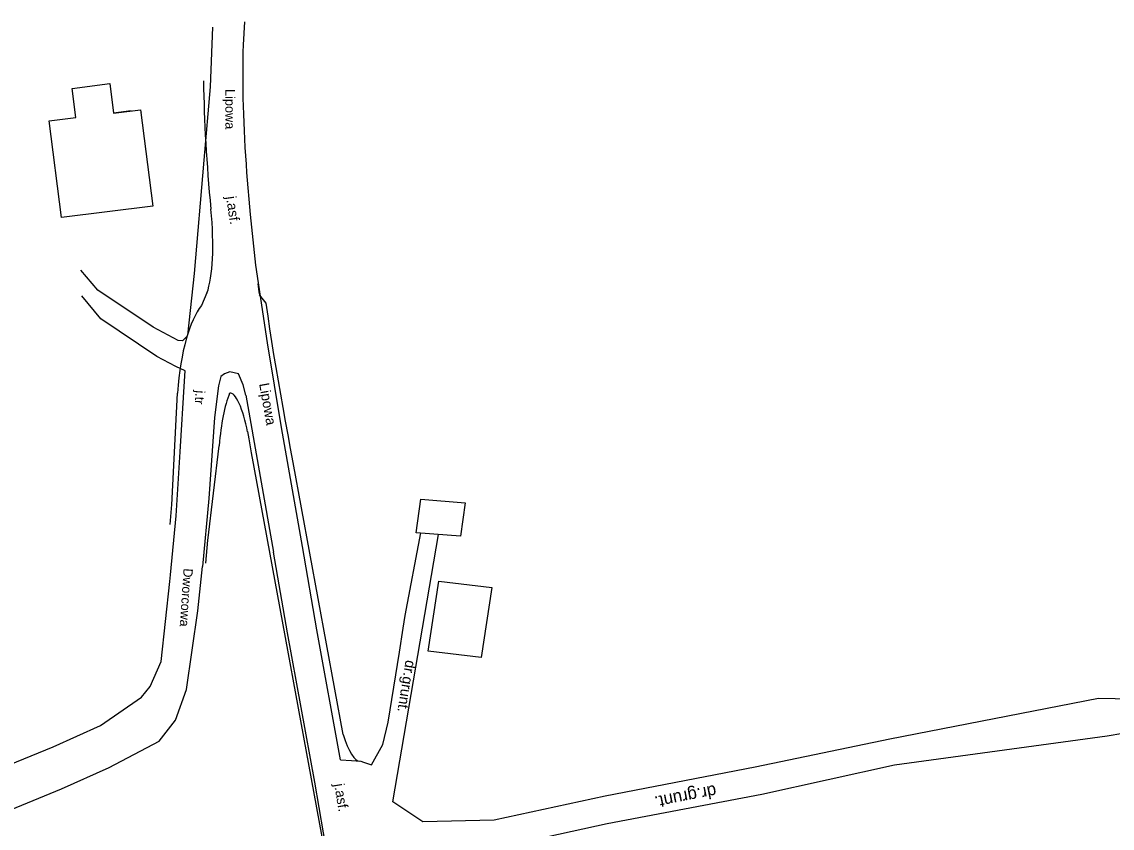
# Model space of a CAD drawing. Extents: x 6541740 to 6556805, y 5525233 to 5530361.
# Drawn here: x 6555210.5 to 6555318.7, y 5525816.1 to 5525896.2 of the extents above; entities that cross this region are included whole.
import ezdxf

# ---------------------------------------------------------------- set-up
doc = ezdxf.new("R2010")
doc.units = 0
for name, color, linetype in [('Default', 7, 'Continuous'), ('TOR_SCH-budynki', 7, 'Continuous'), ('TOR_SCH-przejazdy+drogi istniejace', 7, 'Continuous'), ('TOR_SCH-przejazdy+drogi projektowane', 7, 'Continuous')]:
    doc.layers.add(name, color=color, linetype=linetype)

# ---------------------------------------------------------------- blocks, each defined once
blk = doc.blocks.new('POINT_DISPLAY')
at = {"layer": 'Default'}
blk.add_line((0, 0), (0, 0), dxfattribs=at)

msp = doc.modelspace()

# ---------------------------------------------------------------- linework, layer by layer
at = {"layer": 'TOR_SCH-budynki'}
for p, q in [((6555215.47, 5525889.61), (6555219.19, 5525890.1)), ((6555215.84, 5525886.73), (6555215.47, 5525889.61)), ((6555219.19, 5525890.1), (6555219.58, 5525887.16)), ((6555219.58, 5525887.16), (6555222.23, 5525887.47)), ((6555221.31, 5525887.37), (6555219.58, 5525887.16)), ((6555222.23, 5525887.47), (6555223.46, 5525877.9)), ((6555213.19, 5525886.39), (6555215.84, 5525886.73)), ((6555214.4, 5525876.79), (6555213.19, 5525886.39)), ((6555223.46, 5525877.9), (6555214.4, 5525876.79))]:
    msp.add_line(p, q, dxfattribs=at)
at = {"layer": 'TOR_SCH-przejazdy+drogi istniejace'}
for p, q in [((6555232.56, 5525896.22), (6555232.43, 5525893.93)), ((6555229.21, 5525889.76), (6555229.43, 5525895.67)), ((6555232.72, 5525859.15), (6555235.45, 5525843.55)), ((6555249.61, 5525845.48), (6555250.09, 5525848.82)), ((6555250.09, 5525848.82), (6555254.48, 5525848.44)), ((6555254.48, 5525848.44), (6555254.03, 5525845.12)), ((6555247.29, 5525818.75), (6555251.82, 5525845.3)), ((6555254.03, 5525845.12), (6555249.61, 5525845.48)), ((6555250.82, 5525833.71), (6555251.88, 5525840.66)), ((6555251.88, 5525840.66), (6555257.13, 5525840.03)), ((6555257.13, 5525840.03), (6555256.08, 5525833.07)), ((6555256.08, 5525833.07), (6555250.82, 5525833.71)), ((6555250.28, 5525816.78), (6555247.29, 5525818.75))]:
    msp.add_line(p, q, dxfattribs=at)
for points in [[(6555226.95, 5525865.09), (6555227.62, 5525871.21), (6555228.56, 5525882.48), (6555229.21, 5525889.76)], [(6555238.33, 5525844.11), (6555236.23, 5525855.93), (6555234.85, 5525864.33), (6555233.71, 5525872.05), (6555233.18, 5525877.09), (6555232.8, 5525881.24)], [(6555226.9, 5525865.04), (6555226.4, 5525864.55), (6555225.97, 5525864.57), (6555223.49, 5525865.89), (6555218.02, 5525869.57), (6555216.33, 5525871.56)], [(6555226.68, 5525861.54), (6555225.75, 5525861.98), (6555223.87, 5525862.97), (6555218.31, 5525866.71), (6555216.41, 5525869.01)], [(6555225.23, 5525841.31), (6555225.78, 5525847.17), (6555226.19, 5525853.52), (6555226.62, 5525860.54), (6555226.68, 5525861.54)], [(6555232.72, 5525859.15), (6555232.72, 5525859.15), (6555232.72, 5525859.15), (6555232.72, 5525859.15), (6555232.43, 5525860.18), (6555232.43, 5525860.18), (6555231.99, 5525861.25), (6555231.13, 5525861.47), (6555230.59, 5525861.25), (6555230.21, 5525860.99), (6555229.98, 5525860.05), (6555229.58, 5525856.91), (6555229.02, 5525848.89), (6555228.4, 5525842.13)], [(6555242.11, 5525822.92), (6555243.21, 5525822.87), (6555244.13, 5525822.79), (6555244.38, 5525822.68), (6555245.19, 5525822.42), (6555246.29, 5525824.46), (6555246.82, 5525826.67), (6555247.95, 5525833.6), (6555248.34, 5525836), (6555248.54, 5525837.24), (6555248.54, 5525837.24), (6555248.54, 5525837.24), (6555250.09, 5525845.45)], [(6555242.11, 5525822.92), (6555239.76, 5525835.82), (6555238.33, 5525844.11)], [(6555242.64, 5525802.98), (6555241.29, 5525810.65), (6555239.54, 5525820.69), (6555236.84, 5525835.55), (6555235.45, 5525843.55)], [(6555204.25, 5525815.4), (6555209.33, 5525817.96), (6555214.41, 5525820.04), (6555219.12, 5525822.16), (6555224.09, 5525824.77), (6555225.71, 5525826.86), (6555226.81, 5525829.89), (6555227.94, 5525837.73), (6555228.4, 5525842.13)], [(6555222.33, 5525829.16), (6555223.19, 5525830.2), (6555224.3, 5525832.7), (6555225.16, 5525840.62), (6555225.23, 5525841.31)], [(6555203.38, 5525819.56), (6555208.47, 5525822.12), (6555213.56, 5525824.21), (6555218.26, 5525826.32), (6555222.33, 5525829.16), (6555222.33, 5525829.16)], [(6555325.66, 5525828.85), (6555317.37, 5525829), (6555296.66, 5525824.99), (6555283.28, 5525822.19), (6555268.39, 5525819.31), (6555257.37, 5525816.94), (6555250.28, 5525816.78)], [(6555245.93, 5525814.97), (6555247.4, 5525814.66), (6555250.39, 5525814.05), (6555257.86, 5525814.24), (6555268.58, 5525816.61), (6555283.95, 5525819.5), (6555297.12, 5525822.42), (6555318.23, 5525825.3), (6555325.99, 5525826.63)]]:
    msp.add_lwpolyline(points, dxfattribs=at)
msp.add_ellipse((6555248.81, 5525861.66), major_axis=(-9.92, 52.33), ratio=0.25, start_param=0.859678, end_param=1.140992, dxfattribs=at)
at = {"layer": 'TOR_SCH-przejazdy+drogi projektowane'}
for p, q in [((6555228.84, 5525869.29), (6555228.31, 5525868.03)), ((6555225.36, 5525848.26), (6555225.91, 5525859.35)), ((6555228.92, 5525844.69), (6555230.06, 5525854.1)), ((6555225.2, 5525846.3), (6555225.36, 5525848.29)), ((6555228.73, 5525842.44), (6555228.92, 5525844.73))]:
    msp.add_line(p, q, dxfattribs=at)
for points in [[(6555242.37, 5525825.45), (6555237.41, 5525852.45), (6555237.41, 5525852.45), (6555237.15, 5525853.83), (6555236.9, 5525855.21), (6555236.65, 5525856.57), (6555236.41, 5525857.92), (6555236.17, 5525859.25), (6555235.94, 5525860.57), (6555235.72, 5525861.88), (6555235.5, 5525863.18), (6555235.3, 5525864.46), (6555235.1, 5525865.73), (6555234.91, 5525866.98), (6555234.72, 5525868.29), (6555234.06, 5525869.11)], [(6555232.86, 5525855.52), (6555232.99, 5525854.81), (6555233.25, 5525853.4), (6555233.51, 5525852), (6555233.51, 5525852), (6555241.02, 5525811.14), (6555245.34, 5525787.61)]]:
    msp.add_lwpolyline(points, dxfattribs=at)
for centre, major_axis, ratio, start_param, end_param in [((6555245.31, 5525861.57), (-10.16, 53.6), 0.25, 0.957356, 1.219726), ((6555225.11, 5525881.74), (-2.61, 13.76), 0.25, 3.535525, 4.361319), ((6555234.46, 5525868.35), (-0.64, 3.37), 0.077712, 0.981263, 1.329129), ((6555236.21, 5525835.65), (-6.33, 33.41), 0.25, 0.206288, 0.735906), ((6555237.93, 5525835.98), (-4.84, 25.55), 0.25, 0.372321, 0.735165), ((6555231.87, 5525855.41), (-0.74, 3.93), 0.25, 4.687304, 6.305327), ((6555243.1, 5525827.7), (0.93, -4.91), 0.25, 5.141085, 6.260854)]:
    msp.add_ellipse(centre, major_axis=major_axis, ratio=ratio, start_param=start_param, end_param=end_param, dxfattribs=at)

# ---------------------------------------------------------------- block references
at = {"layer": 'TOR_SCH-budynki', "xscale": 0.7652750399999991, "yscale": 0.7652750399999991}
msp.add_blockref('POINT_DISPLAY', (6555222.37, 5525887.23), dxfattribs=at)

# ---------------------------------------------------------------- texts
at = {"layer": 'TOR_SCH-przejazdy+drogi istniejace'}
for s, height, rotation, p in [('Lipowa', 0.942, 270.0823, (6555230.67, 5525889.54)), ('j.asf.', 1, 278.3885, (6555230.74, 5525878.83)), ('Lipowa', 1, 280.075, (6555234.02, 5525860.26)), ('j.tr', 0.931, 265.9886, (6555227.73, 5525859.63)), ('Dworcowa', 0.928, 266.1027, (6555226.53, 5525841.96)), ('dr.grunt.', 1.045, 260.7644, (6555248.58, 5525832.87)), ('j.asf.', 1, 279.3688, (6555241.47, 5525820.49)), ('dr.grunt.', 1.249, 190.9995, (6555279.3, 5525820.44))]:
    msp.add_text(s, height=height, rotation=rotation, dxfattribs=at).set_placement(p)

doc.saveas('drawing.dxf')
